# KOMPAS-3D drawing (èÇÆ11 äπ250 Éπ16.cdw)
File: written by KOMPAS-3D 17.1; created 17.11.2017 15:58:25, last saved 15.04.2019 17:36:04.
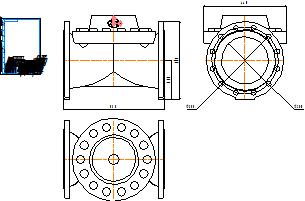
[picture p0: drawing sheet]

Sheet 1: A4, portrait

Title block, sheet 1: name: КАТ11 Ду250 Ру16; material: Внимание! Данный продукт является объектом авторского права ООО «Торговый Дом АДЛ». / Запрещается изменение, копирование, распространение / (в том числе путем копирования на другие сайты и ресурсы в Интернете) / или любое иное использование информации и объектов без предварительного / согласия правообладателя (ООО «Торговый Дом АДЛ»).; mass: 12,4; sheets: 1; organisation: ООО "Торговый дом АДЛ"; sheet format: A4; stored path: \\adlc.lan\data\АДЛ_ПКД\3D-модели\ADL production\Клапаны КАТ ГРАНРЕГ\КАТ11\KOMPAS 2D\КАТ11 Ду250 Ру16.cdw

Views: Вид 1, Проекционный вид 2, Проекционный вид 3
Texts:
  kka
  adl
Dimensions and other numbers on the sheet: 535; 205; 410; 355; 440; 250; 1:1; 1; 12,4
